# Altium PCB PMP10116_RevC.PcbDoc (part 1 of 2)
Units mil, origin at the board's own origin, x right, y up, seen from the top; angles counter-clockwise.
Board outline 9441.58 x 3500 mil, 2 copper layers (Top Layer, Bottom Layer), stack 62 mil thick; 153 components, 82 nets, 354 pads, 48 vias.
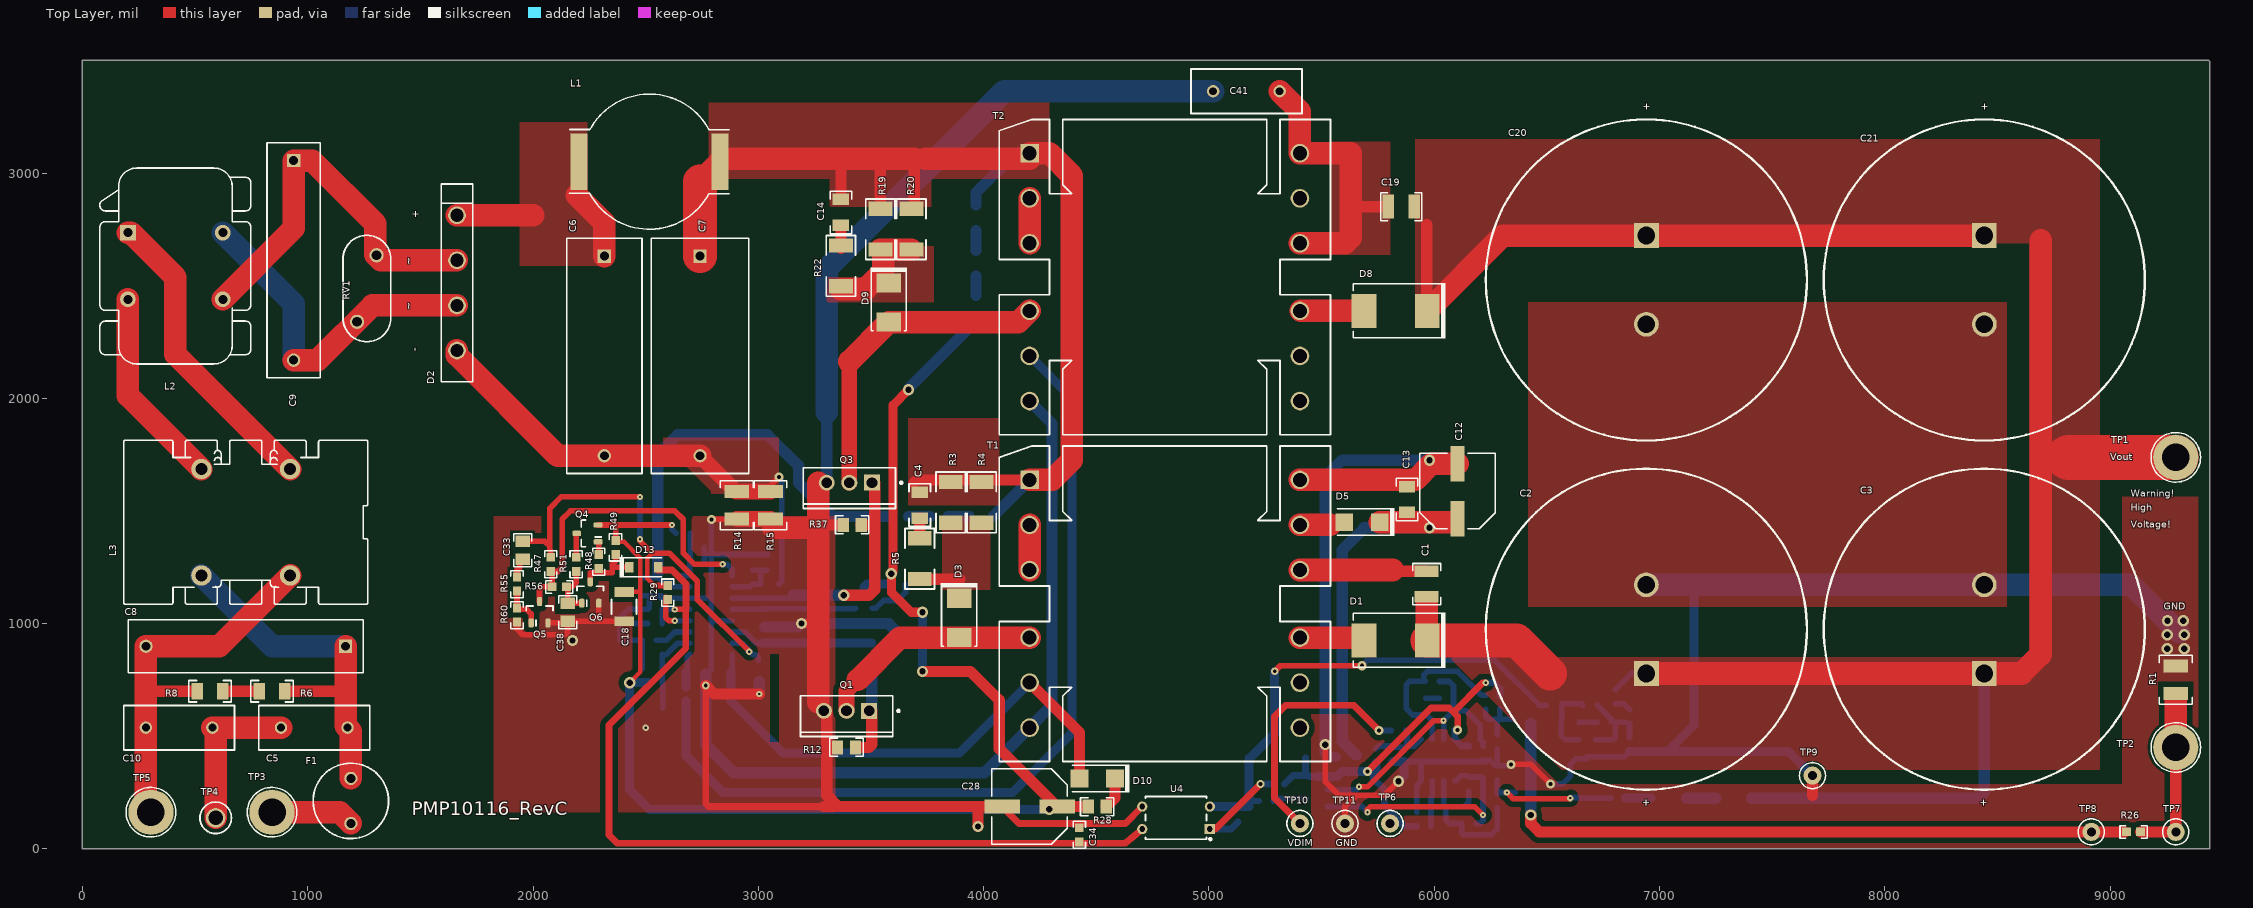
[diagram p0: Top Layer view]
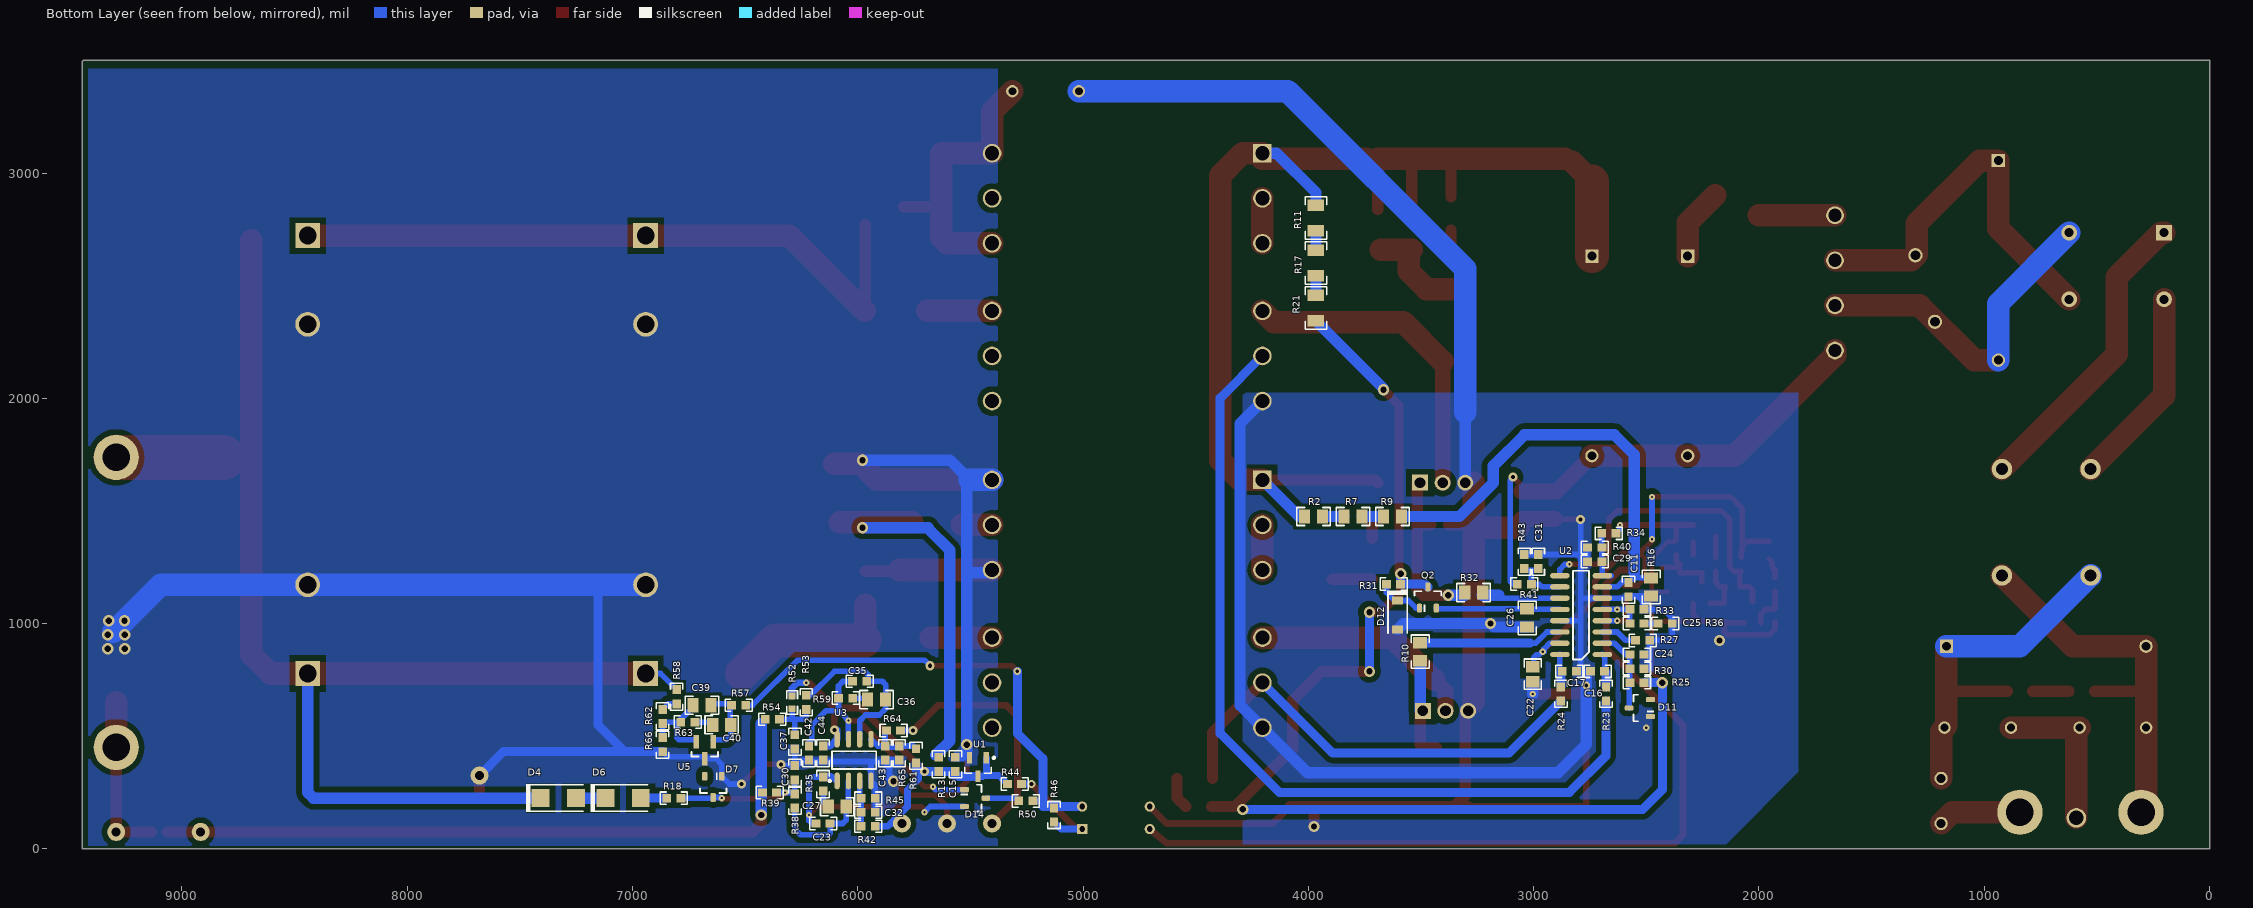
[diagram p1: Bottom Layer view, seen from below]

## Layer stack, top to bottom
Top Solder: solder mask 0.4, Solder Resist, Dk 3.5
Top Layer: signal copper 1.4
Dielectric1: core 59.2, FR-4, Dk 4.8
Bottom Layer: signal copper 1.4
Bottom Solder: solder mask 0.4, Solder Resist, Dk 3.5

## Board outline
0,0 9441.58,0 9441.58,3495.92 9437.5,3500 0,3500

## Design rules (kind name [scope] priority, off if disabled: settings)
AcuteAngle [All] p1: minimum=4.50000000000000E+0001 checktracksonly=FALSE
AssemblyTestPointUsage [All] p1: valid=2
Clearance Clearance_Keepouts [((IsTrack Or IsArc) And Not InPoly) And IsFree and IsKeepOut vs ((IsTrack Or IsArc) And Not InPoly) And IsFree and IsKeepOut] p1: gap=0
Clearance Clearance_BoardEdge_MountingHoles [OnCopper and InComponentClass('Mounting Holes') vs IsKeepOut] p2: gap=20
Clearance Clearance_BoardEdge_Poly [OnCopper and InPoly vs IsKeepOut] p3: gap=25
Clearance Clearance_BoardEdge [OnCopper and Not InComponentClass('Logo') and not InComponentClass('FiducialMark') and not InRegion(1000,500,4000,800) and Not IsKeepout vs IsKeepOut] p4: gap=75
Clearance Clearance_Poly [InPolygon] p5: gap=25
Clearance [All] p6: gap=7.87
ComponentClearance ComponentClearance_MountingHoles_FiducialMarks [InComponentClass('Mounting Holes') vs InComponentClass('FiducialMark')] p1: gap=20 collisioncheckmode=3 verticalgap=10 showdistances=FALSE
ComponentClearance ComponentClearance_Shunt [InComponentClass('Header') vs InComponentClass('Shunt')] p2: gap=0 collisioncheckmode=3 verticalgap=0 showdistances=FALSE
ComponentClearance ComponentClearance_Logo [InComponentClass('Logo')] p3: gap=50 collisioncheckmode=3 verticalgap=10 showdistances=FALSE
ComponentClearance ComponentClearance_ScrewToNut [(HasFootprint('NY PMS 440 0025 PH')) vs (HasFootprint('Keystone_1902C'))] p4: gap=5 collisioncheckmode=3 verticalgap=10 showdistances=FALSE
ComponentClearance ComponentClearance_MountingHoles [InComponentClass('Mounting Holes')] p5: gap=20 collisioncheckmode=3 verticalgap=100000 showdistances=FALSE
ComponentClearance ComponentClearance_SmallPassives [HasFootprint('0201*') or HasFootprint('0402*') or HasFootprint('0508') or HasFootprint('0603*') or HasFootprint('0612') or HasFootprint('0805*') or HasFootprint('0815*') or HasFootprint('0830*') or HasFootprint('1206*') or HasFootprint('1210*') or HasFootprint('1808*') or HasFootprint('1812*') or HasFootprint('1825*') or HasFootprint('2010*') or HasFootprint('2220*') or HasFootprint('2225*') or HasFootprint('2512*') or HasFootprint('2728*') or HasFootprint('3518*') vs HasFootprint('0201*') or HasFootprint('0402*') or HasFootprint('0508') or HasFootprint('0603*') or HasFootprint('0612') or HasFootprint('0805*') or HasFootprint('0815*') or HasFootprint('0830*') or HasFootprint('1206*') or HasFootprint('1210*') or HasFootprint('1808*') or HasFootprint('1812*') or HasFootprint('1825*') or HasFootprint('2010*') or HasFootprint('2220*') or HasFootprint('2225*') or HasFootprint('2512*') or HasFootprint('2728*') or HasFootprint('3518*')] p6: gap=20 collisioncheckmode=3 verticalgap=10 showdistances=FALSE
ComponentClearance ComponentClearance_THtoSMT [IsThruComponent vs IsSMTComponent] p7: gap=20 collisioncheckmode=3 verticalgap=10 showdistances=FALSE
ComponentClearance ComponentClearance_THtoTH [IsThruComponent vs IsThruComponent] p8: gap=20 collisioncheckmode=3 verticalgap=10 showdistances=FALSE
ComponentClearance [All] p9: gap=20 collisioncheckmode=3 verticalgap=10 showdistances=FALSE
DiffPairsRouting [All] p1: maxlimit=100 minlimit=10 mostfreqgap=10 toplayer_minwidth=15 toplayer_maxwidth=15 toplayer_prefwidth=15 bottomlayer_minwidth=15 bottomlayer_maxwidth=15 bottomlayer_prefwidth=15 maxuncoupledlength=1000
FabricationTestPointUsage TestPointUsage [All] p1: valid=2 allowmultiple=FALSE
FabricationTestpoint Testpoint [All] p1: side=3 testpointundercomponent=TRUE minsize=40 maxsize=100 preferedsize=60 minholesize=0 maxholesize=40 preferedholesize=32 testpointgrid=1 allowsidetop=TRUE allowsidebottom=TRUE usegrid=TRUE gridtolerance=0.01
FanoutControl Fanout_LCC [IsLCC] p1: bgadir=Out bgaviamode=Centered fanoutstyle=Auto fanoutdirection=Alternating viagrid=1 // Fanout_LCC (Default Rule)
FanoutControl Fanout_BGA [IsBGA] p2: bgadir=Out bgaviamode=Centered fanoutstyle=Auto fanoutdirection=Alternating viagrid=1 // Fanout_BGA (Default Rule)
FanoutControl Fanout_Default [All] p4: bgadir=Out bgaviamode=Centered fanoutstyle=Auto fanoutdirection=Alternating viagrid=1 // Fanout_Default (Default Rule)
FanoutControl Fanout_Small [(CompPinCount < 5)] p5: bgadir=Out bgaviamode=Centered fanoutstyle=Auto fanoutdirection=OutThenIn viagrid=1 // Fanout_Small (Default Rule)
Height [All] p1: minheight=0 maxheight=10000 prefheight=500
HoleSize [All] p1: absolutevalues=TRUE maxlimit=251 minlimit=8 maxpercent=80.000 minpercent=20.000
MinimumAnnularRing MinimumAnnularRing_ThermalPadVias [IsVia and InAnyComponent] p1: minimumring=5.91
MinimumAnnularRing [All] p2: minimumring=9
MinimumSolderMaskSliver MinimumSolderMaskSliver_Logo [InComponentClass('Logo') vs InComponentClass('Logo')] p1: minsoldermaskwidth=0.7
MinimumSolderMaskSliver [All] p2: minsoldermaskwidth=3.94
PlaneConnect [All] p1: planeconnectstyle=Relief reliefexpansion=10 reliefentries=4 reliefconductorwidth=10 reliefairgap=10
PolygonConnect [All] p1: connectstyle=Direct reliefconductorwidth=10 reliefentries=4 polygonreliefangle="90 Angle" airgapwidth=10
RoutingVias ThermalPadVias [IsVia and InAnyComponent] p1: holewidth=7.87 width=19.68 viastyle="Through Hole" minholewidth=7.87 minwidth=19.68 maxholewidth=12.99 maxwidth=23.62
RoutingVias [All] p2: holewidth=16 width=34 viastyle="Through Hole" minholewidth=7.87 minwidth=26 maxholewidth=40 maxwidth=65
SilkToBoardRegionClearance [Not ((IsComment or IsDesignator) And (Hide <> 'False')) and not InRegion(1000,500,4000,800)] p1 off:
SilkToSilkClearance SilkToSilkClearance_Pb-FreeLogo [(HasFootprint('Pb-Free_Overlay_Medium') OR HasFootprint('Pb-Free_Overlay_Small')) vs (HasFootprint('Pb-Free_Overlay_Medium') OR HasFootprint('Pb-Free_Overlay_Small'))] p1 off: silktosilkclearance=0
SilkToSilkClearance [All] p2 off: silktosilkclearance=5
SilkToSolderMaskClearance "Silk to Solder Mask Opening" [All] p1 off: minsilkscreentomaskgap=1 clearancetoexposedcopper=FALSE
SolderMaskExpansion [All] p1: expansion=1.97
UnpouredPolygon [All] p1: allowunpoured=FALSE
Width [All] p1: maxlimit=200 minlimit=6 preferedwidth=10 checkconnectedcopper=TRUE
13 further rules are at their usual default settings.

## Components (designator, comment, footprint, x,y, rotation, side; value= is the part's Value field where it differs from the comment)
C1 "Used in BOM report" 1210 5966.58,1175.66 r90 top
C2 "EKMQ351VSN471MA30S" KMQ_3500x3000 6941.58,975.66 r90 top
C3 "EKMQ351VSN471MA30S" KMQ_3500x3000 8441.58,975.66 r90 top
C4 "GRM31BR72J472KW01L" 1206 3716.58,1525.66 r270 top
C5 "VY2472M49Y5US63V7" VY2_1250x500x1650 1029.08,538.16 r180 top
C6 "B32923C3474M" B32923_16.5mm 2316.58,2188.16 r270 top
C7 "B32923C3105M" B32923_20.5mm 2741.58,2188.16 r270 top
C8 "B32923C3224K" B32923_15mm 725,900 r180 top
C9 "B32923C3224K" B32923_15mm 937.5,2612.5 r270 top
C10 "VY2472M49Y5US63V7" VY2_1250x500x1650 429.08,538.16 r180 top
C11 "06035A102KAT2A" 0603 2579.08,1150.66 r270 bottom
C12 "EEE-FC1E470P" SM_RADIAL_E 6104.08,1588.16 r90 top
C13 "Used in BOM report" 1206 5879.08,1550.66 r90 top
C14 "GRM31BR72J472KW01L" 1206 3366.58,2825.66 r270 top
C15 "06035C104KAT2A" 0603 5566.58,375.66 r90 bottom
C16 "GRM1885C1H820JA01D" 0603 2716.58,788.16 r0 bottom
C17 "GRM1885C1H820JA01D" 0603 2841.58,788.16 r0 bottom
C18 "C3225X7R1H225K250AB" 1210_280 2404.08,1075.66 r270 top
C19 "Used in BOM report" 1210 5854.08,2850.66 r180 top
C20 "EKMQ351VSN471MA30S" KMQ_3500x3000 6941.58,2525.66 r270 top
C21 "EKMQ351VSN471MA30S" KMQ_3500x3000 8441.58,2525.66 r270 top
C22 "C1608X7R1H224K080AB" 0805 3004.08,775.66 r270 bottom
C23 "GRM188R71E153KA01D" 0603 6154.08,113.16 r180 bottom
C24 "C0603C103J5RACTU" 0603 2541.58,863.16 r180 bottom
C25 "C1608X7R1H104K" 0603 2541.58,1000.66 r180 bottom
C26 "C2012X7R1H105K125AB" 0805_HV 3029.08,1025.66 r270 bottom
C27 "0805YC474KAT2A" 0805_HV 6091.58,188.16 r0 bottom
C28 "EEE-FC1E470P" SM_RADIAL_E 4204.08,188.16 r180 top
C29 "C0603C103J5RACTU" 0603 2729.08,1275.66 r0 bottom
C30 "GRM188R71H103KA01D" 0603 6279.08,338.16 r90 bottom
C31 "06035A220JAT2A" 0603 2979.08,1275.66 r90 bottom
C32 "GRM188R71H103KA01D" 0603 5954.08,163.16 r180 bottom
C33 "GRM21BR71H474KA88L" 0805_HV 1954.08,1325.66 r270 top
C34 "GRM188R71H471KA01D" 0603 4425,62.5 r90 top
C35 "GRM188R71E153KA01D" 0603 5991.58,744.66 r180 bottom
C36 "0805YC474KAT2A" 0805_HV 5916.58,663.16 r0 bottom
C37 "GRM188R71H103KA01D" 0603 6279.08,475.66 r270 bottom
C38 "GRM216R71H103KA01D" 0805_HV 2154.08,1050.66 r270 top
C39 "08055C473JAT2A" 0805_HV 6691.58,638.16 r0 bottom
C40 "C2012X5R1E475K125AB" 0805_HV 6604.08,550.66 r180 bottom
C41 "VY2472M49Y5US63V7" VY2_1250x500x1650 5166.58,3363.16 r0 top
C42 "C1608C0G1H101J" 0603 6216.58,425.66 r270 bottom
C43 "06035C104KAT2A" 0603 5879.08,425.66 r270 bottom
C44 "GRM188R71H103KA01D" 0603 6154.08,425.66 r90 bottom
D1 "STTH212S" SMC 5829.08,925.66 r180 top
D2 "GBU4G" GBU 1662.5,2512.5 r270 top
D3 "STTH2R06U" SMB 3891.58,1025.66 r270 top
D4 "3smaj5953b" SMA 7329.08,225.66 r180 bottom
D5 "SS110-TP" SMA 5679.08,1450.66 r180 top
D6 "3smaj5953b" SMA 7041.58,225.66 r180 bottom
D7 "MMBZ5230BLT1G" SOT-23 6641.58,275.66 r270 bottom
D8 "STTH212S" SMC 5829.08,2388.16 r180 top
D9 "STTH2R06U" SMB 3579.08,2425.66 r270 top
D10 "SS110-TP" SMA 4504.08,313.16 r180 top
D11 "MMBZ5231BLT1G" SOT-23 2529.08,625.66 r0 bottom
D12 "MMSZ5248B-7-F" SOD-123 3604.08,1038.16 r270 bottom
D13 "1N4148W-TP" SOD-123 2491.58,1250.66 r0 top
D14 "BAT54A-7-F" SOT-23 5479.08,225.66 r180 bottom
F1 "38312000000" FUSE_372 1191.58,213.16 r270 top
L1 "DO5010H-334MLB" DO5010H 2516.58,3050.66 r0 top
L2 "744823220" IND_WE-CMB_M 412.5,2587.5 r0 top
L3 "744824310" IND_WE-CMB_L 725,1450 r180 top
Q1 "SPP11N80C3" TO-220FP 3391.58,613.16 r270 top
Q2 "MMBT3904LT1G" SOT-23 3469.45,1116.04 r90 bottom
Q3 "SPP11N80C3" TO-220FP 3404.08,1625.66 r270 top
Q4 "MMBT3906-7-F" SOT-23 2241.58,1400.66 r180 top
Q5 "MMBT3904" SOT-23 2029.08,1050.66 r90 top
Q6 "MMBT3904" SOT-23 2254.08,1138.16 r90 top
R1 "MCR25JZHFLR510" 1210M 9291.58,750.66 r90 top
R2 "CRCW08052M00FKEA" 0805_HV 3977.01,1475.66 r0 bottom
R3 "CRCW2010200KJNEF" 2010 3854.08,1538.16 r90 top
R4 "CRCW2010200KJNEF" 2010 3991.58,1538.16 r90 top
R5 "CRCW201020R0FKEF" 2010 3716.58,1288.16 r90 top
R6 "CRCW1206470KJNEA" 1206 841.58,700 r0 top
R7 "CRCW08052M00FKEA" 0805_HV 3802.01,1475.66 r0 bottom
R8 "CRCW1206470KJNEA" 1206 566.58,700 r0 top
R9 "CRCW08052M00FKEA" 0805_HV 3627.01,1475.66 r0 bottom
R10 "CRCW080510R0FKEA" 0805_HV 3504.08,875.66 r270 bottom
R11 "CRCW1206200KFKEA" 1206 3966.58,2800.66 r90 bottom
R12 "CRCW080510K0FKEA" 0805_HV 3391.58,450.66 r0 top
R13 "CRCW06031K50FKEA" 0603 5641.58,375.66 r90 bottom
R14 "ERJ-L14KF10CU" 1210M 2904.08,1525.66 r90 top
R15 "ERJ-L14KF10CU" 1210M 3054.08,1525.66 r90 top
R16 "CRCW080542K2FKEA" 0805_HV 2479.08,1163.16 r90 bottom
R17 "CRCW1206200KFKEA" 1206 3966.58,2600.66 r90 bottom
R18 "CRCW060349K9FKEA" 0603 6816.58,225.66 r0 bottom
R19 "CRCW2010200KJNEF" 2010 3541.58,2750.66 r90 top
R20 "CRCW2010200KJNEF" 2010 3679.08,2750.66 r90 top
R21 "CRCW1206200KFKEA" 1206 3966.58,2400.66 r90 bottom
R22 "CRCW201020R0FKEF" 2010 3366.58,2588.16 r90 top
R23 "CRCW060336K5FKEA" 0603 2679.08,688.16 r90 bottom
R24 "CRCW060336K5FKEA" 0603 2879.08,688.16 r90 bottom
R25 "CRCW0603100KFKEA" 0603 2541.58,738.16 r180 bottom
R26 "CRCW060349R9FKEA" 0603 9104.08,75.66 r0 top
R27 "CRCW0603100KFKEA" 0603 2516.58,925.66 r0 bottom
R28 "CRCW080510R0FKEA" 0805_HV 4504.08,188.16 r0 top
R29 "CRCW06030000Z0EA" 0603 2597.78,1138.16 r270 top
R30 "CRCW060357K6FKEA" 0603 2541.58,800.66 r0 bottom
R31 "CRCW06031K00FKEA" 0603 3621.99,1175.66 r180 bottom
R32 "CRCW080510R0FKEA" 0805_HV 3266.58,1138.16 r0 bottom
R33 "CRCW060360K4FKEA" 0603 2541.58,1063.16 r0 bottom
R34 "CRCW060382K5FKEA" 0603 2666.58,1400.66 r180 bottom
R35 "CRCW0603100KFKEA" 0603 6154.08,288.16 r90 bottom
R36 "Used in BOM report" 0603 2416.58,1000.66 r0 bottom
R37 "CRCW080510K0FKEA" 0805_HV 3416.58,1438.16 r0 top
R38 "RC0603FR-0749K9L" 0603 6279.08,213.16 r270 bottom
R39 "CRCW06032K00FKEA" 0603 6391.58,250.66 r0 bottom
R40 "CRCW060318K2FKEA" 0603 2729.08,1338.16 r180 bottom
R41 "CRCW0603100RFKEA" 0603 3041.58,1175.66 r0 bottom
R42 "CRCW0603499KFKEA" 0603 5954.08,100.66 r180 bottom
R43 "CRCW0603100RFKEA" 0603 3041.58,1275.66 r270 bottom
R44 "CRCW06031K00FKEA" 0603 5304.08,288.16 r180 bottom
R45 "CRCW060343K2FKEA" 0603 5954.08,225.66 r0 bottom
R46 "CRCW06031K00FKEA" 0603 5129.08,150.66 r270 bottom
R47 "CRCW060310K0FKEA" 0603 2079.08,1263.16 r90 top
R48 "CRCW060310K0FKEA" 0603 2291.58,1275.66 r90 top
R49 "CRCW0603200RFKEA" 0603 2366.58,1338.16 r90 top
R50 "RC0603FR-072KL" 0603 5254.08,213.16 r180 bottom
R51 "CRCW060310K0FKEA" 0603 2191.58,1263.16 r90 top
R52 "Used in BOM report" 0603_HV 6291.58,650.66 r90 bottom
R53 "RC0603FR-0749K9L" 0603 6229.08,650.66 r90 bottom
R54 "CRCW06032K00FKEA" 0603 6379.08,575.66 r0 bottom
R55 "CRCW0603100KFKEA" 0603 1929.08,1175.66 r90 top
R56 "CRCW06031K00FKEA" 0603 2116.58,1163.16 r180 top
R57 "CRCW06030000Z0EA" 0603 6529.08,638.16 r0 bottom
R58 "CRCW060349R9FKEA" 0603 6804.08,675.66 r270 bottom
R59 "CRCW0603100KFKEA" 0603 6054.08,669.66 r0 bottom
R60 "CRCW0603100KFKEA" 0603 1929.08,1038.16 r90 top
R61 "Used in BOM report" 0603 5741.58,413.16 r270 bottom
R62 "CRCW0603200KFKEA" 0603 6866.58,588.16 r90 bottom
R63 "CRCW060315K0FKEA" 0603 6754.08,563.16 r180 bottom
R64 "CRCW0603301KFKEA" 0603 5841.58,525.66 r180 bottom
R65 "CRCW060311K3FKEA" 0603 5816.58,425.66 r90 bottom
R66 "CRCW06032K43FKEA" 0603 6866.58,463.16 r90 bottom
RV1 "S20K275" VAR_S10K275E2 1262.5,2487.5 r90 top
T1 "750315289" WURTH_750315289_90 4804.08,1088.16 r0 top
T2 "750315290" WURTH_750315289_90 4804.08,2538.16 r0 top
TP1 "Suggest using a net name here" Keystone1503-2 9291.58,1738.16 r0 top
TP2 "Suggest using a net name here" Keystone1503-2 9291.58,450.66 r0 top
TP3 "Suggest using a net name here" Keystone1503-2 841.58,163.16 r90 top
TP4 "5011" Keystone5011 591.58,138.16 r90 top
TP5 "Suggest using a net name here" Keystone1503-2 304.08,163.16 r90 top
TP6 "5000" Keystone5000 5804.08,113.16 r0 top
TP7 "5000" Keystone5000 9291.58,75.66 r0 top
TP8 "5000" Keystone5000 8916.58,75.66 r0 top
TP9 "5001" Keystone5001 7679.08,325.66 r90 top
TP10 "5000" Keystone5000 5404.08,113.16 r0 top
TP11 "5001" Keystone5001 5604.08,113.16 r0 top
U1 "LM4040AIM3-5.0/NOPB" MF03A_N 5466.58,363.16 r270 bottom
U2 "UCC28063" D0016A_N 2789.51,1038.16 r0 bottom
U3 "LMV358M" M08A_L 6016.58,394.65 r90 bottom
U4 "FOD817A" DIP-4 4854.08,138.16 r180 top
U5 "TL431AIDBZT" DBZ0003A_N 6679.08,438.16 r270 bottom

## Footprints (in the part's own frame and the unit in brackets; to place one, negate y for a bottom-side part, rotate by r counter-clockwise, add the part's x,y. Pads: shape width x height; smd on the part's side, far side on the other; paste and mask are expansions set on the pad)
0603 [mm] "0603 from SM-752 data"
  rect 1x0.95 smd: 1(-0.8,0) 2(0.8,0)
  silkscreen extent -1.52,-0.69 1.52,0.69, body extent -0.87,-0.47 0.87,0.47, height 0.85
0603_HV [mil] "Ernesto recommended land pattern.  26 mil between pads."
  rect 30x30 smd: 1(-28,0) 2(28,0)
  silkscreen extent -52,-24 52,24, body extent -34,-19 34,19, height 33
0805 [mm] "0805 from SM-752 data"
  rect 1.3x1.5 smd: 1(-0.85,0) 2(0.85,0)
  silkscreen extent -1.72,-0.97 1.72,0.97, body extent -1.1,-0.72 1.1,0.72, height 1.1
0805_HV [mil] "0805 with 30mil clearance between pads"
  rect 50x63 smd: 1(-40,0) 2(40,0)
  silkscreen extent -74,-40 74,40, body extent -43,-29 43,29, height 43
1206 [mm] "1206 from SM-752 data"
  rect 1.3x1.85 smd: 1(-1.45,0) 2(1.45,0)
  silkscreen extent -2.4,-1.21 2.4,1.21, body extent -1.7,-0.9 1.7,0.9, height 1.35
1210 [mm] "1210 from SM-752 data"
  rect 1.3x2.7 smd: 1(-1.45,0) 2(1.45,0)
  silkscreen extent -2.32,-1.57 2.32,1.57, body extent -1.7,-1.35 1.7,1.35, height 1.35
1210_280 [mm] "SMD, 2-Leads, Body 3.6x2.8mm, Height 2.8mm"
  rect 1.1x2.2 smd: 1(-1.65,0) 2(1.65,0)
  silkscreen extent -0.84,-1.4 0.84,1.4, body extent -1.8,-1.4 1.8,1.4, height 2.8
1210M [mm] "1210 from SM-752 data"
  rect 1.5x2.8 smd: 1(-1.55,0) 2(1.55,0)
  silkscreen extent -2.75,-1.85 2.75,1.85, body extent -1.7,-1.35 1.7,1.35, height 1.35
2010 [mm] "Chip Capacitor, Body 5.08x2.54mm, IPC Medium Density"
  rect 1.6x2.7 smd: 1(-2.3,0) 2(2.3,0)
  silkscreen extent -3.42,-1.65 3.42,1.65, body extent -2.73,-1.45 2.73,1.45, height 1.66
B32923_15mm [mm] "Epcos film capacitors, 22.5mm spacing"
  rect 1.5x1.5 hole 1: 1(-11.25,0)
  round 1.5 hole 1: 2(11.25,0)
  silkscreen extent -13.25,-3 13.25,3, body extent -13.25,-3 13.25,3, height 15
B32923_16.5mm [mm] "Epcos film capacitors, 22.5mm spacing"
  rect 1.5x1.5 hole 1: 1(-11.25,0)
  round 1.5 hole 1: 2(11.25,0)
  silkscreen extent -13.25,-4.25 13.25,4.25, body extent -13.25,-4.25 13.25,4.25, height 16.5
B32923_20.5mm [mm] "Epcos film capacitors, 22.5mm spacing"
  rect 1.5x1.5 hole 1: 1(-11.25,0)
  round 1.5 hole 1: 2(11.25,0)
  silkscreen extent -13.25,-5.5 13.25,5.5, body extent -13.25,-5.5 13.25,5.5, height 20.5
D0016A_N [mm] "SOIC, 16-Leads, Body 9.9x3.9mm, Pitch 1.27mm, IPC Medium Density"
  oval 2.2x0.6 smd: 1(-2.4,4.445) 2(-2.4,3.175) 3(-2.4,1.905) 4(-2.4,0.635) 5(-2.4,-0.635) 6(-2.4,-1.905) 7(-2.4,-3.175) 8(-2.4,-4.445) 9(2.4,-4.445) 10(2.4,-3.175) 11(2.4,-1.905) 12(2.4,-0.635) 13(2.4,0.635) 14(2.4,1.905) 15(2.4,3.175) 16(2.4,4.445)
  silkscreen extent -0.9,-5 0.9,5, body extent -3,-4.95 3,4.95, height 1.59
DBZ0003A_N [mm] "SOT23, 3-Leads, Body 2.9x1.3mm, Pitch 0.95mm, Lead Span 2.4mm, IPC Medium Density"
  rect 1.5x0.6 smd: 1(-0.95,0.95) 2(-0.95,-0.95) 3(0.95,0)
  silkscreen extent 0.2,-1.5 0.7,1.5, body extent -1.26,-1.46 1.26,1.46, height 0.96
DIP-4 [mm] "DIP, 4-Leads, Body 6.86x4.83mm, Pitch 2.54mm"
  rect 1.15x1.15 hole 0.65: 1(-3.81,1.27)
  round 1.15 hole 0.65: 2(-3.81,-1.27) 3(3.81,-1.27) 4(3.81,1.27)
  silkscreen extent -4,-2.41 3.43,2.52, body extent -4.02,-2.41 4.02,2.41, height 5.59
DO5010H [mm] "Coilcraft recommended land pattern.  Document 284-2, rev 10/14/08"
  rect 1.9x6.35 smd: 1(-7.95,0) 2(7.95,0)
  silkscreen extent -9.01,-7.62 9,7.62, body extent -9.02,-7.64 9.02,7.6, height 8.32
FUSE_372 [mm] "LITTELFUSE"
  round 1.5 hole 1: 1(-2.54,0) 2(2.54,0)
  silkscreen extent -4.25,-4.25 4.25,4.25, body extent -4.26,-4.26 4.26,4.26, height 8
GBU [mm] "Comchip / Diodes Inc diode bridge"
  round 2 hole 1.5: 1(-7.62,0) 2(-2.54,0) 3(2.54,0) 4(7.62,0)
  silkscreen extent -11.15,-1.78 11.15,1.78, body extent -11.15,-1.76 11.15,1.8, height 21.55
IND_WE-CMB_L [mm] "Wurth"
  round 2.3 hole 1.321: 2(-5,6) 4(5,6) 7(5,-6) 9(-5,-6)
  silkscreen extent -13.75,-9.25 13.75,9.25, body extent -13.75,-9.25 13.75,9.25, height 33.02
IND_WE-CMB_M [mil] "Wurth"
  rect 70x70 hole 40: 1(-210.63,147.64)
  round 70 hole 40: 2(210.63,147.64) 3(210.63,-147.64) 4(-210.63,-147.64)
  silkscreen extent -335,-435 335,435, body extent -335,-394 335,394, height 1044
Keystone1503-2 [mm] "Double Turret"
  round 5.1 hole 3.1: 1(0,0)
  silkscreen extent -2.79,-2.79 2.79,2.79, body extent -2.4,-2.4 2.38,2.4, height 9.22
Keystone5000 [mil] "For Keystone 500x miniature loop terminals"
  round 80 hole 40: 1(0,0)
  silkscreen extent -58,-58 58,58, body extent -49,-49 49,49, height 182
Keystone5001 [mil] "For Keystone 500x miniature loop terminals"
  round 80 hole 40: 1(0,0)
  silkscreen extent -58,-58 58,58, body extent -49,-49 49,49, height 182
Keystone5011 [mil] "Keystone Multipurpose loops"
  round 87 hole 63: 1(0,0)
  silkscreen extent -70,-70 70,70, body extent -63,-63 63,62, height 319
KMQ_3500x3000 [mm] "TH, 2-Leads, 35 mm Dia, Pin Spacing 10 mm"
  rect 2.8x2.8 hole 2: 1(-5,0)
  round 2.8 hole 2: 2(5,0)
  silkscreen extent -18.1,-18.1 18.1,18.1, body extent -17.86,-17.97 17.94,17.97, height 32.01
M08A_L [mm] "SOIC, 8-Leads, Body 4.9x3.9mm, Pitch 1.27mm, IPC High Density"
  oval 1.9x0.6 smd: 1(-2.35,1.905) 2(-2.35,0.635) 3(-2.35,-0.635) 4(-2.35,-1.905) 5(2.35,-1.905) 6(2.35,-0.635) 7(2.35,0.635) 8(2.35,1.905)
  silkscreen extent -2.47,-2.5 1,2.88, body extent -2,-2.5 2,2.5, height 1.75
MF03A_N [mm] "SOT23, 3-Leads, Body 2.9x1.3mm, Pitch 0.95mm, Lead Span 2.4mm, IPC Medium Density"
  rect 1.3x0.6 smd: 1(-1.05,0.95) 2(-1.05,-0.95) 3(1.05,0)
  silkscreen extent -1.17,-1.5 0.7,1.92, body extent -0.7,-1.5 0.7,1.5, height 1.12
SM_RADIAL_E [mm] "8 x 6.2mm:  Panasonic E"
  rect 4x1.6 smd: 1(-3.1,0) 2(3.1,0)
  silkscreen extent -4.25,-4.25 4.25,4.25, body extent -4.26,-4.26 4.26,4.26, height 6.5
SMA [mm] "Molded Diode, 2-Leads, Body 4.3x2.6mm, IPC Medium Density, based on OnSemi component dimensions and land pattern"
  rect 2x2 smd: 1(-2,0) 2(2,0)
  silkscreen extent -3.66,-1.57 2.79,1.57, body extent -2.6,-1.3 2.6,1.3, height 2.42
SMB [mil] "Molded Diode, 2-Leads, Body 5.4x3.6mm, IPC Medium Density, based on OnSemi component dimensions"
  rect 85x107.99 smd: 1(-87.01,0) 2(87.01,0)
  silkscreen extent -155,-82 125,82, body extent -106,-71 106,71, height 91
SMC [mil] "Molded Diode, 2-Leads, Body 6.9x5.8mm, IPC Medium Density, based on OnSemi component dimensions and land patterns"
  rect 110x150 smd: 1(-140.49,0) 2(140.49,0)
  silkscreen extent -221,-124 189,123, body extent -156,-116 156,116, height 91
SOD-123 [mm] "On Semi recommended land pattern"
  rect 0.915x1.22 smd: 1(-1.637,0) 2(1.637,0)
  silkscreen extent -2.74,-1.17 2.03,1.17, body extent -1.93,-0.9 1.93,0.9, height 1.35
SOT-23 [mm] "SOT23, 3-Leads, Body 2.9x1.3mm, Pitch 0.95mm, Lead Span 2.5mm, IPC Medium Density"
  rrect50% 1x0.6 smd: 1(-1.2,0.95) 2(-1.2,-0.95) 3(1.2,0)
  silkscreen extent -1.63,-1.5 0.7,1.5, body extent -1.16,-1.45 1.21,1.45, height 1
TO-220FP [mm] "FM, Body 10.4x4.6mm, Pitch 2.55mm"
  rect 1.8x1.8 hole 1.2: 1(0,2.55)
  round 1.8 hole 1.2: 2(0,0) 3(0,-2.55)
  silkscreen extent -1.69,-5.2 2.91,5.98, body extent -1.69,-5.2 2.91,5.2, height 20
VAR_S10K275E2 [mm] "EPCOS"
  round 1.6 hole 1.1: 1(-3.75,1.1) 2(3.75,-1.1)
  silkscreen extent -6,-2.7 6,2.7, body extent -5.98,-2.7 5.98,2.7, height 14.99
VY2_1250x500x1650 [mm] "TH, 2- Leads, Body 12.5x5mm, Pin Spacing 7.5mm"
  round 1.4 hole 0.9: 1(-3.75,0) 2(3.75,0)
  silkscreen extent -6.25,-2.5 6.25,2.5, body extent -6.2,-2.5 6.25,2.5, height 16.49
WURTH_750315289_90 [mm] "TH, 12-Leads, Body 37.34x35.56mm"
  rect 2.1x2.1 hole 1.6: 1(-15.24,13.97)
  round 2.1 hole 1.6: 2(-15.24,8.89) 3(-15.24,3.81) 4(-15.24,-3.81) 5(-15.24,-8.89) 6(-15.24,-13.97) 7(15.24,-13.97) 8(15.24,-8.89) 9(15.24,-3.81) 10(15.24,3.81) 11(15.24,8.89) 12(15.24,13.97)
  silkscreen extent -18.67,-17.78 18.67,17.78, body extent -18.67,-17.8 18.67,17.8, height 24.13

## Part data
C1 C13 C19: library part Capacitor, "CAP, CERM, xxxF, xxV, [TempCo], xx%, [PackageReference]"
C2 C3 C20 C21: "CAP, AL, 470 µF, 350 V, +/- 20%,  ohm, TH"
C4 C14: "CAP, CERM, 4700 pF, 630 V, +/- 10%, X7R, 1206"
C5 C10 C41: "CAP, CERM, 4700 pF, 440 V, +/- 20%, Y5U, TH, 12.5x5mm"
C6: "CAP, Film, 0.47 µF, 630 V, +/- 20%, TH"
C7: "CAP, Film, 1 µF, 630 V, +/- 20%, 0.018 ohm, TH"
C8 C9: "CAP, Film, 0.22 µF, 630 V, +/- 10%, TH"
C11: "CAP, CERM, 1000 pF, 50 V, +/- 10%, C0G/NP0, 0603"
C12 C28: "CAP, AL, 47uF, 25V, +/-20%, 0.4 ohm, SMD"
C15 C43: "CAP, CERM, 0.1uF, 50V, +/-10%, X7R, 0603"
C16 C17: "CAP, CERM, 82 pF, 50 V, +/- 5%, C0G/NP0, 0603"
C18: "CAP, CERM, 2.2 µF, 50 V, +/- 10%, X7R, 1210"
C22: library part GRM21BR71H224KA01L, "CAP, CERM, 0.22 µF, 50 V, +/- 10%, X7R, 0805"
C23 C35: "CAP, CERM, 0.015 µF, 25 V, +/- 10%, X7R, 0603"
C24 C29: "CAP, CERM, 0.01 µF, 50 V, +/- 5%, X7R, 0603"
C25: "CAP, CERM, 0.1 µF, 50 V, +/- 10%, X7R, 0603"
C26: "CAP, CERM, 1 µF, 50 V, +/- 10%, X7R, 0805"
C27 C36: "CAP, CERM, 0.47 µF, 16 V, +/- 10%, X7R, 0805"
C30 C32 C37 C44: "CAP, CERM, 0.01uF, 50V, +/-10%, X7R, 0603"
C31: "CAP, CERM, 22 pF, 50 V, +/- 5%, C0G/NP0, 0603"
C33: "CAP, CERM, 0.47 µF, 50 V, +/- 10%, X7R, 0805"
C34: "CAP, CERM, 470 pF, 50 V, +/- 10%, X7R, 0603"
C38: "CAP, CERM, 0.01 µF, 50 V, +/- 10%, X7R, 0805"
C39: "CAP, CERM, 0.047 µF, 50 V, +/- 5%, X7R, 0805"
C40: "CAP, CERM, 4.7 µF, 25 V, +/- 10%, X5R, 0805"
C42: "CAP, CERM, 100 pF, 50 V, +/- 5%, C0G/NP0, 0603"
D1 D8: library part MURS360T3G, "Diode, Ultrafast, 1200V, SMC"
D2: library part GBU4K-E3/45, "Diode, Switching-Bridge, 400 V, 4 A, TH"
D3 D9: library part STTH1R06U, "Diode, Superfast Rectifier, 600 V, 2A, SMB"
D4 D6: library part 3SMAJ5941B-TP, "Diode, Zener, 150 V, 3 W, SMA"
D5 D10: "Diode, Schottky, 100V, 1A, SMA"
D7: "Diode, Zener, 4.7V, 225mW, SOT-23"
D11: "Diode, Zener, 5.1 V, 225 mW, SOT-23"
D12: "Diode, Zener, 18 V, 500 mW, SOD-123"
D13: "Diode, Switching, 100 V, 0.15 A, SOD-123"
D14: "Diode, Schottky, 30 V, 0.2 A, SOT-23"
F1: library part 37211000001, "Fuse, 2A, 300 V, TH"
L1: "Inductor, Drum Core, Ferrite, 330 µH, 1 A, 0.56 ohm, SMD"
L2: library part 744823210, "Coupled inductor, 20 mH,"
L3: "Coupled inductor, 10 mH, 3 A, 0.105 ohm, +/- 30%, TH"
Q1 Q3: library part SPA11N80C3, "MOSFET, N-CH, 800 V, 11 A, TO-220FP"
Q2: library part "MMBT3904LT1G, ON Semiconductor", "Transistor, NPN, 40V, 0.2A, SOT-23"
Q4: library part "MMBT3906-7-F, Diodes Inc.", "Transistor, PNP, 40 V, 0.2 A, SOT-23"
Q5 Q6: library part "MMBT3904, Fairchild Semiconductor", "Transistor, NPN, 40 V, 0.2 A, SOT-23"
R1: "RES, 0.51 ohm, 1%, 0.5W, 1210"
R2 R7 R9: "RES, 2.00 M, 1%, 0.125 W, 0805"
R3 R4 R19 R20: "RES, 200 k, 5%, 0.75 W, 2010"
R5 R22: "RES, 20.0, 1%, 0.75 W, 2010"
R6 R8: "RES, 470 k, 5%, 0.25 W, 1206"
R10 R32: "RES, 10.0, 1%, 0.125 W, 0805"
R11 R17 R21: "RES, 200k ohm, 1%, 0.25W, 1206"
R12 R37: "RES, 10.0 k, 1%, 0.125 W, 0805"
R13: "RES, 1.50k ohm, 1%, 0.1W, 0603"
R14 R15: "RES, 0.1, 1%, 0.33 W, 1210"
R16: "RES, 42.2 k, 1%, 0.125 W, 0805"
R18 R38 R53: "RES, 49.9 k, 1%, 0.1 W, 0603"
R23 R24: "RES, 36.5 k, 1%, 0.1 W, 0603"
R25 R27 R35 R55 R59 R60: "RES, 100 k, 1%, 0.1 W, 0603"
R26 R58: "RES, 49.9 ohm, 1%, 0.1W, 0603"
R28: "RES, 10.0 ohm, 1%, 0.125W, 0805"
R29: "RES, 0, 5%, 0.1 W, 0603"
R30: "RES, 57.6 k, 1%, 0.1 W, 0603"
R31 R46: "RES, 1.00k ohm, 1%, 0.1W, 0603"
R33: "RES, 60.4 k, 1%, 0.1 W, 0603"
R34: "RES, 82.5 k, 1%, 0.1 W, 0603"
R36 R52 R61: library part Resistor, "RES, xxx ohm, x%, xW, [PackageReference]"
R39 R54: "RES, 2.00k ohm, 1%, 0.1W, 0603"
R40: "RES, 18.2 k, 1%, 0.1 W, 0603"
R41 R43: "RES, 100, 1%, 0.1 W, 0603"
R42: "RES, 499k ohm, 1%, 0.1W, 0603"
R44 R56: "RES, 1.00 k, 1%, 0.1 W, 0603"
R45: "RES, 43.2k ohm, 1%, 0.1W, 0603"
R47 R48 R51: "RES, 10.0 k, 1%, 0.1 W, 0603"
R49: "RES, 200, 1%, 0.1 W, 0603"
R50: "RES, 2.00 k, 1%, 0.1 W, 0603"
R57: "RES, 0 ohm, 5%, 0.1W, 0603"
R62: "RES, 200 k, 1%, 0.1 W, 0603"
R63: "RES, 15.0 k, 1%, 0.1 W, 0603"
R64: "RES, 301k ohm, 1%, 0.1W, 0603"
R65: "RES, 11.3k ohm, 1%, 0.1W, 0603"
R66: "RES, 2.43 k, 1%, 0.1 W, 0603"
RV1: library part S10K275E2, "Varistor 275V RMS 10MM Radial, TH"
T1 T2: "Transformer, 400 uH, TH"
TP1 TP2 TP3 TP5: library part 1503-2, "Terminal, Turret, TH, Double"
TP4: "Test Point, Multipurpose, Black, TH"
TP6 TP7 TP8 TP10: "Test Point, Miniature, Red, TH"
TP9 TP11: "Test Point, Miniature, Black, TH"
U1: "Precision Micropower Shunt Voltage Reference, 3-pin SOT-23, Pb-Free"
U2: library part UCC28060D, "IC, Interleave PFC Controller"
U3: "General Purpose, Low Voltage, R-R Out, 1MHz Dual Op Amp"
U4: "High Operating Temperature Phototransistor Optocoupler, DIP-4"
U5: "Adjustable Precision Shunt Regulator, 34 ppm / degC, 100 mA, -40 to 85 degC, 3-pin SOT-23 (DBZ), Green (RoHS & no Sb/Br)"

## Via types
v1: diameter 50, hole 28, Top Layer to Bottom Layer, 21 vias
v2: diameter 28, hole 10, Top Layer to Bottom Layer, 16 vias
v3: diameter 40, hole 18, Top Layer to Bottom Layer, 8 vias
v4: diameter 34, hole 16, Top Layer to Bottom Layer, 3 vias

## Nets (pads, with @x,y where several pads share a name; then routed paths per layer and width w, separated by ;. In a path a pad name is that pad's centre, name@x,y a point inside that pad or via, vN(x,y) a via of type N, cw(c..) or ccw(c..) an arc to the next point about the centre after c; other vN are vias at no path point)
CS: C6.2 C7.2 D2.4 R14.2 R15.2 R41.2 | length 2243.1
  Top Layer w25: R14.2@2905.55,1575.66 R14.2@2916.58,1586.68 ; R15.2@3054.08,1586.68 3054.08,1613.16 v3(3091.58,1650.66)
  Top Layer w50: R14.2@2904.08,1586.68 R14.2@2916.58,1586.68
  Top Layer w70: C7.2@2741.58,1745.25 2900.14,1586.68 R14.2@2904.08,1586.68 ; R14.2@2916.58,1586.68 R15.2@3054.08,1586.68
  Top Layer w100: D2.4@1662.5,2212.5 1662.5,2192.23 2109.49,1745.25 C6.2@2316.58,1745.25 C7.2@2741.58,1745.25
  Bottom Layer w25: R41.2@3091.58,1175.66 3104.08,1188.16 3104.08,1635.9 3091.58,1648.4 v3(3091.58,1650.66)
GND: C1.2 C2.2 C3.2 C12.2 C13.2 C15.2 C19.2 C20.2 C21.2 C30.2 C32.2 C37.2 C41.2 C42.2 C43.2 C44.1 D7.1 R1.2 R45.1 R65.1 R66.1 T1.10 T1.12 T2.12 TP9.1 TP11.1 U1.2 U3.4 U5.3 | length 10992.2
  Top Layer w25: v1(5516.58,463.16) 5516.58,298.89 5577.3,238.16 5654.08,238.16 ; TP11.1@5604.08,113.16 5604.08,188.16 5654.08,238.16 ; v1(5841.58,300.66) 5779.08,238.16 5654.08,238.16 ; v3(6341.58,375.66) 6429.08,375.66 v3(6516.58,288.16)
  Top Layer w50: 5641.58,2850.66 C19.2@5796.99,2850.66 ; 5846.99,1232.75 C1.2@5966.58,1232.75 ; 7679.08,238.16 TP9.1@7679.08,325.66
  Top Layer w100: C41.2@5314.21,3363.16 5404.08,3273.3 T2.12@5404.08,3088.16 5629.08,3088.16 5629.08,2713.16 5604.08,2688.16 5404.08,2688.16 ; T1.10@5404.08,1238.16 5816.58,1238.16 ; T1.12@5404.08,1638.16 5916.58,1638.16 5988.62,1710.21 C12.2@6104.08,1710.21
  Bottom Layer w25: C43.2@5866.58,388.16 5941.58,388.16 ; C32.2@5922.58,163.16 R45.1@5922.58,225.66 5922.58,283.14 U3.4@5941.58,302.14 5941.58,388.16 ; C42.2@6216.58,394.16 6245.87,394.16 6270.38,369.65 C30.2@6279.08,369.65 ; C42.2@6229.08,388.16 5941.58,388.16 ; C37.2@6279.08,444.16 C30.2@6279.08,369.65 ; v3(6341.58,375.66) 6335.57,369.65 C30.2@6279.08,369.65 ; v3(6516.58,288.16) 6569.43,288.16 D7.1@6604.17,322.9 6604.17,375.76 6629.17,400.76 U5.3@6679.08,400.76 ; U5.3@6679.08,409.91 6844.82,409.91 R66.1@6866.58,431.66
  Bottom Layer w40: 5535.57,407.15 C15.2@5566.58,407.15 ; R65.1@5816.58,388.16 5866.58,388.16 5866.58,325.66 v1(5841.58,300.66) ; R66.1@6866.58,431.66 7035.08,431.66 ; 7166.58,1172.51 7154.08,1160.01 7154.08,550.66 7035.08,431.66 ; TP9.1@7679.08,325.66 7573.07,431.66 7035.08,431.66
  Bottom Layer w50: T1.10@5416.58,1225.66 5516.58,1225.66 ; 5516.58,425.66 v1(5516.58,463.16) 5516.58,1225.66 ; v1(5979.08,1725.66) 5591.58,1725.66 5516.58,1650.66 5516.58,1225.66
  Bottom Layer w100: T1.12@5404.08,1638.16 5504.08,1638.16 ; C2.2@6941.58,1172.51 7166.58,1172.51 C3.2@8441.58,1172.51 9094.73,1172.51 9304.08,963.16
  other v1: 9254.08,888.16 9329.08,888.16 9254.08,950.66 9329.08,950.66 9254.73,1012.5 9325,1012.5
NetC4_1: C4.1 C7.1 C14.1 L1.2 R2.2 R3.2 R4.2 R11.2 R19.2 R20.2 T1.1 T2.1 | length 5161.7
  Top Layer w50: C14.1@3366.58,2895.25 3366.58,3050.66 ; R19.2@3541.58,2858.14 3541.58,3063.16 ; 3691.58,1625.66 3704.08,1638.16 T1.1@4204.08,1638.16 ; R20.2@3691.58,2838.45 3691.58,3063.16
  Top Layer w100: 2741.58,2962.67 L1.2@2829.57,3050.66 ; L1.2@2861.58,3063.16 3541.58,3063.16 3691.58,3063.16 ; 3741.58,3063.16 T2.1@4204.08,3063.16 ; T1.1@4204.08,1638.16 4304.08,1638.16 4391.58,1725.66 4391.58,2988.16 4291.58,3088.16 T2.1@4204.08,3088.16
  Top Layer w150: C7.1@2741.58,2631.07 2741.58,2962.67
  Bottom Layer w50: R11.2@3966.58,2857.75 3966.58,2913.16 4141.58,3088.16 T2.1@4204.08,3088.16 ; R2.2@4041.58,1475.66 T1.1@4204.08,1638.16
NetC4_2: C4.2 R5.2 | length 89.9
  Top Layer w50: R5.2@3716.58,1378.71 C4.2@3716.58,1468.57
NetC5_1: C5.1 C8.1 F1.1 L3.4 R6.2 | length 1635.6
  Top Layer w50: R6.2@898.66,700 1167.91,700
  Top Layer w100: C8.1@1167.91,900 1167.91,700 1167.91,546.96 C5.1@1176.71,538.16 1191.58,523.3 F1.1@1191.58,313.16
  Bottom Layer w100: L3.4@528.15,1213.78 841.93,900 C8.1@1167.91,900
NetC5_2: C5.2 C10.1 TP4.1 | length 689.9
  Top Layer w100: C10.1@576.71,538.16 C5.2@881.44,538.16 ; TP4.1@591.58,138.16 C10.1@591.58,523.3
NetC6_1: C6.1 D2.1 L1.1 | length 657.5
  Top Layer w100: D2.1@1662.5,2812.5 2000,2812.5 ; 2194.88,2900.66 2316.58,2778.96 C6.1@2316.58,2631.07
NetC8_2: C8.2 C10.2 L3.2 R8.1 TP5.1 | length 1743.4
  Top Layer w50: 281.44,700 R8.1@509.49,700
  Top Layer w100: C8.2@281.44,899.35 281.44,700 C10.2@281.44,538.16 281.44,231.06 304.08,208.42 TP5.1@304.08,163.16 ; C8.2@282.09,900 608.07,900 L3.2@921.85,1213.78
NetC9_1: C9.1 D2.2 L2.3 RV1.2 | length 1716.9
  Top Layer w100: L2.3@623.13,2439.86 937.5,2754.23 C9.1@937.5,3037.5 ; C9.1@937.5,3055.41 1019.59,3055.41 1300,2775 1300,2637.5 1325,2612.5 D2.2@1662.5,2612.5
NetC9_2: C9.2 D2.3 L2.2 RV1.1 | length 1521.4
  Top Layer w100: C9.2@937.5,2169.59 1044.59,2169.59 1287.5,2412.5 D2.3@1662.5,2412.5
  Bottom Layer w100: L2.2@623.13,2735.14 937.5,2420.77 C9.2@937.5,2169.59
NetC12_1: C12.1 C13.1 D5.1 R13.2 | length 1687
  Top Layer w100: D5.1@5757.82,1450.66 C12.1@6079.08,1450.66
  Bottom Layer w50: R13.2@5654.08,417.03 5591.58,479.53 5591.58,1325.66 5687.58,1421.66 5687.58,1425.66 v1(5979.08,1425.66)
NetC14_2: C14.2 R22.2 | length 80
  Top Layer w50: R22.2@3366.58,2666.21 C14.2@3366.58,2746.23
NetC16_1: C16.1 R23.2 U2.1 | length 141.6
  Bottom Layer w25: C16.1@2685.08,788.16 2685.08,853.22 U2.1@2695.02,863.16
  Bottom Layer w40: R23.2@2679.08,719.65 C16.1@2679.08,782.16
NetC17_2: C17.2 R24.2 U2.16 | length 142
  Bottom Layer w25: C17.2@2873.07,788.16 2884,799.08 U2.16@2884,863.16
  Bottom Layer w40: R24.2@2879.08,719.65 C17.2@2879.08,782.15
NetC23_1: C23.1 D14.2 R35.2 U3.1 | length 1089
  Top Layer w25: v2(5704.08,163.16) 5704.08,175.66 5716.58,188.16 6179.08,188.16 v2(6216.58,150.66)
  Bottom Layer w25: D14.2@5526.32,188.26 5678.98,188.26 v2(5704.08,163.16) ; U3.1@6091.58,302.14 6095.41,302.14 6118.94,325.66 R35.2@6148.07,325.66 ; R35.2@6154.08,319.65 6210.08,319.65 6216.58,313.16 v2(6216.58,150.66) 6216.58,125.66 6204.08,113.16 C23.1@6185.57,113.16
NetC23_2: C23.2 C27.1 R38.2 U3.2 | length 547.7
  Bottom Layer w25: C27.1@6041.58,198.16 U3.2@6041.58,302.14 ; C27.1@6051.58,188.16 6051.58,128.16 6066.58,113.16 C23.2@6122.58,113.16 6122.58,69.65 6129.08,63.16 6254.08,63.16 6279.08,88.16 R38.2@6279.08,181.66
NetC24_1: C24.1 D11.3 R25.1 R30.2 U2.2 | length 363
  Bottom Layer w25: C24.1@2573.07,863.16 R30.2@2573.07,800.66 R25.1@2573.07,738.16 2576.32,734.91 D11.3@2576.32,625.66 ; C24.1@2591.58,863.16 2641.58,913.16 U2.2@2695.02,913.16
NetC25_1: C25.1 C34.1 D13.2 R33.2 U2.5 U4.4 | length 4044.7
  Top Layer w25: v2(2629.08,1063.16) 2679.08,1063.16
  Top Layer w30: D13.2@2554.08,1238.16 2616.58,1238.16 2679.08,1175.66 2679.08,1063.16 2678.02,1062.1 2678.02,890.52 2337.5,550 2337.5,62.5 2375,25 2562.5,25 4425,25.59 4629.08,25.66 U4.4@4704.08,88.16
  Bottom Layer w25: C25.1@2573.07,1000.66 R33.2@2573.07,1063.16 v2(2629.08,1063.16) U2.5@2695.02,1063.16
NetC25_2: C25.2 R36.2 | length 62
  Bottom Layer w25: R36.2@2448.07,1000.66 C25.2@2510.08,1000.66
